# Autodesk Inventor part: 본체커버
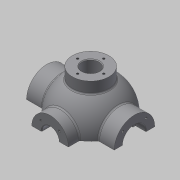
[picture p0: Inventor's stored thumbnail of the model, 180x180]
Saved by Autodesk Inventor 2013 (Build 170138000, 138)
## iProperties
Created: 2015-12
Part Number: 본체커버
Material: 일반
Document SubType Name: Modeling
Designer: mduedu
Density: 1 g/cm^3
Mass: 211.839 g
Surface Area: 451.737 cm^2
Volume: 211.839 cm^3
Author: mduedu
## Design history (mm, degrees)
sketch "스케치1"
  geometry: L1 (-53, 0)-(53, 0); A1 r 53 centre (0, 0) between (53, 0) and (-53, 0); 2 further points
  constraints: 2 coincident, 2 end point, 2 point on circle, 1 centre point, 1 horizontal, 1 midpoint
  dimensions: "d0" = 53 radius of A1
revolve "회전1" sketch "스케치1" stored, may be unused: angle "d2" = 90 deg
feature "쉘1" dims "d11" = 10
node "작업 평면1"
sketch "스케치2"
  geometry: C1 r 31 at (0, 0); 1 further point
  constraints: 1 centre point, 1 coincident
  dimensions: "d4" = 62 diameter of C1
extrude "돌출1" join sketch "스케치2" stored distance "d5" = 10; taper "d6" = 0 deg
node "작업 평면2"
sketch "스케치3"
  geometry: C1 r 28 at (0, 0); 1 further point
  constraints: 1 centre point, 1 coincident
  dimensions: "d8" = 56 diameter of C1
extrude "돌출2" join sketch "스케치3" stored distance "d9" = 10; taper "d10" = 0 deg
hole "구멍1" diameter "d14" = 35; stored, may be unused: countersink angle "d18" = 90 deg, drill point angle "d20" = 0 deg; dims "d12" = 10, "d13" = 10, "d15" = 6, "d16" = 4, "d17" = 2, "d19" = 16
hole "구멍2" diameter "d23" = 27; stored, may be unused: countersink angle "d27" = 90 deg, drill point angle "d29" = 0 deg; dims "d21" = 10, "d22" = 10, "d24" = 6, "d25" = 4, "d26" = 2, "d28" = 16
fillet "모깎기1" dims "d30" = 0.3
hole "구멍3" diameter "d33" = 26; stored, may be unused: countersink angle "d37" = 90 deg, drill point angle "d39" = 0 deg; dims "d31" = 10, "d32" = 10, "d34" = 6, "d35" = 4, "d36" = 2, "d38" = 16
chamfer "모따기1" distance "d40" = 1; stored, may be unused: second distance "d41" = 2, angle "d42" = 45 deg
sketch "스케치4"
  geometry: L1 (0, 0)-(0, -25); L2 (0, 0)-(-17.678, -17.678); A1 r 25 centre (0, 0) between (-17.678, -17.678) and (0, -25); 1 further point
  constraints: 4 end point, 2 point on circle, 1 centre point, 1 coincident, 1 vertical
  dimensions: "d43" = 50 diameter of A1; "d47" = 45 deg angle of L1 L2
hole "구멍4" sketch "스케치4" at (-17.678, -17.678) diameter "d49" = 3.242; stored, may be unused: countersink angle "d53" = 90 deg, drill point angle "d55" = 118 deg; dims "d50" = 11, "d51" = 4, "d52" = 2, "d54" = 13
sketch "스케치5"
  geometry: L1 (0, 0)-(0, -20); L2 (0, 0)-(-14.142, -14.142); A1 r 20 centre (0, 0) between (0, -20) and (-14.142, -14.142); 2 further points
  constraints: 4 end point, 2 coincident, 2 point on circle, 1 centre point, 1 vertical
  dimensions: "d59" = 40 diameter of A1; "d65" = 45 deg angle of L1 L2
hole "구멍5" sketch "스케치5" at (-14.142, -14.142) diameter "d67" = 3.242; stored, may be unused: countersink angle "d71" = 90 deg, drill point angle "d73" = 118 deg; dims "d68" = 8, "d69" = 4, "d70" = 2, "d72" = 10
node "작업 평면3"
sketch "스케치6"
  geometry: C1 r 65 at (0, 0); 1 further point
  constraints: 1 centre point, 1 coincident
  dimensions: "d78" = 130 diameter of C1
extrude "돌출3" join sketch "스케치6" distance "d80" = 10; taper "d81" = 0 deg
sketch "스케치7"
  geometry: C1 r 20 at (0, 0); 1 further point
  constraints: 1 centre point, 1 coincident
  dimensions: "d82" = 40 diameter of C1
extrude "돌출4" join sketch "스케치7" stored distance "d84" = 10; taper "d85" = 0 deg
sketch "스케치8"
  geometry: 2 further points
  constraints: 1 coincident
hole "구멍6" sketch "스케치8" at (0, 0) diameter "d86" = 20; stored, may be unused: countersink angle "d90" = 90 deg, drill point angle "d92" = 118 deg; dims "d87" = 7, "d88" = 40, "d89" = 5, "d91" = 10
fillet "모깎기2" dims "d93" = 0.3
sketch "스케치9"
  geometry: L1 (65, -75)-(-65, -75) reference; L2 (-45, -75)-(-38.245, -36.692); A1 r 53 centre (0, 0) between (42.988, 31) and (42.988, -31) reference; 1 further point
  constraints: 2 end point, 1 point on circle, 1 point on line
  dimensions: "d94" = 45 horizontal distance of L2.start point (0, 0); "d95" = 80 deg angle of L2 L1
feature "리브1" sketch "스케치9" dims "d96" = 1, "d97" = 8, "d98" = 0, "d99" = 0, "d100" = 1, "d101" = 1
sketch "스케치10"
  geometry: L1 (0, 0)-(0, -55); L2 (0, 0)-(-38.891, -38.891); A1 r 55 centre (0, 0) between (0, -55) and (-38.891, -38.891); 2 further points
  constraints: 4 end point, 2 coincident, 2 point on circle, 1 centre point, 1 vertical
  dimensions: "d105" = 110 diameter of A1; "d107" = 45 deg angle of L1 L2
hole "구멍7" sketch "스케치10" at (-38.891, -38.891) diameter "d109" = 10; stored, may be unused: countersink angle "d113" = 90 deg, drill point angle "d115" = 118 deg; dims "d110" = 7, "d111" = 40, "d112" = 5, "d114" = 10
fillet "모깎기3" dims "d120" = 3
fillet "모깎기4" dims "d121" = 3, "d122" = 3
fillet "모깎기5" dims "d123" = 3
fillet "모깎기6" dims "d124" = 3
sketch "스케치11"
  geometry: C1 r 5 at (-38.891, 38.891) reference; C2 r 5 at (38.891, 38.891) reference; C3 r 5 at (38.891, -38.891) reference; C4 r 5 at (-38.891, -38.891) reference; C5 r 20 at (0, 0) reference; C6 r 65 at (0, 0) reference; 1 further point
  constraints: 3 other
feature "엠보싱1" sketch "스케치11" dims "d125" = 0.5, "d126" = 0
sketch "스케치12"
  geometry: L1 (0, 100)-(0, -100); L2 (0, 100)-(-150, 100); L3 (-150, 100)-(-150, -100); L4 (-150, -100)-(0, -100); 2 further points
  constraints: 8 end point, 3 perpendicular, 1 coincident, 1 midpoint, 1 vertical
  dimensions: "d127" = 200 distance of L2.end L3.end; "d129" = 150 distance of L3.end L1.end
extrude "돌출5" cut sketch "스케치12" stored distance "d130" = 10; taper "d131" = 0 deg
sketch "스케치13"
  geometry: C1 r 7 at (0, -53); A1 r 53 centre (0, 0) between (-42.113, -32.179) and (42.113, -32.179) reference; 1 further point
  constraints: 1 centre point, 1 point on circle
  dimensions: "d132" = 14 diameter of C1
extrude "돌출6" join sketch "스케치13" distance "d133" = 5; taper "d134" = 0 deg
sketch "스케치14"
  geometry: C1 r 7 at (0, 0) reference; 1 further point
extrude "돌출7" cut sketch "스케치14" stored distance "d135" = 5; taper "d136" = 0 deg
sketch "스케치15"
  geometry: C1 r 2.25 at (0, 53); A1 r 7 centre (0, 53) between (6.965, 52.302) and (-6.965, 52.302) reference; 1 further point
  constraints: 1 centre point, 1 coincident
  dimensions: "d139" = 4.5 diameter of C1
extrude "돌출8" cut sketch "스케치15" stored distance "d141" = 5; taper "d142" = 0 deg
fillet "모깎기7" dims "d143" = 3
fillet "모깎기8" dims "d144" = 1
fillet "모깎기9" dims "d145" = 1
fillet "모깎기10" dims "d146" = 1
node "작업 평면4"
sketch "스케치16"
  geometry: C1 r 28 at (0, 0); 1 further point
  constraints: 1 centre point, 1 coincident
  dimensions: "d148" = 56 diameter of C1
extrude "돌출9" join sketch "스케치16" stored distance "d150" = 5; taper "d151" = 0 deg
hole "구멍8" diameter "d154" = 26; stored, may be unused: countersink angle "d158" = 90 deg, drill point angle "d160" = 118 deg; dims "d152" = 10, "d153" = 10, "d155" = 6, "d156" = 4, "d157" = 2, "d159" = 8
sketch "스케치17" dims "d161" = 40
  geometry: 3 further points
  constraints: 2 vertical alignment, 1 coincident, 2 other
hole "구멍9" sketch "스케치17" at (0, 20) diameter "d163" = 3.242; stored, may be unused: countersink angle "d167" = 90 deg, drill point angle "d169" = 118 deg; dims "d164" = 8, "d165" = 4, "d166" = 2, "d168" = 10
fillet "모깎기11" dims "d173" = 3
chamfer "모따기2" distance "d174" = 1; stored, may be unused: second distance "d175" = 2, angle "d176" = 45 deg
node "솔리드1"
mirror "대칭1"
mirror "대칭2"
pattern_circular "원형 패턴1" dims angle "d57" = 360 deg
mirror "대칭3"
pattern_circular "원형 패턴2" dims angle "d75" = 360 deg
pattern_circular "원형 패턴3" dims angle "d103" = 360 deg
pattern_circular "원형 패턴4" dims angle "d118" = 360 deg
pattern_circular "원형 패턴5" dims angle "d171" = 360 deg
node "투영된 루프1"
other parameters: "d3" = 67, "d7" = 62, "d77" = -85, "d147" = 62
